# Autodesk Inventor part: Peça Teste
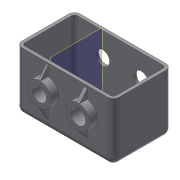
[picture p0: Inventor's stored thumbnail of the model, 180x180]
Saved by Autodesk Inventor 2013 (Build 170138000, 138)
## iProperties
Created: 2013-05
Part Number: Peça Teste
Material: Genérico
Document SubType Name: Modeling
Designer: Draw
Density: 1 g/cm^3
Author: Draw
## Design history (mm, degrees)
sketch "Esboço1"
  geometry: L1 (0, 0)-(500, 0); L2 (500, 0)-(500, 300); L3 (500, 300)-(0, 300); L4 (0, 300)-(0, 0)
  constraints: 8 end point, 2 parallel, 1 horizontal, 1 perpendicular
  dimensions: "d0" = 500 distance of L3.end L2.end; "d1" = 300 distance of L2.end L1.end
extrude "Extrusão1" new body sketch "Esboço1" distance "d2" = 300; taper "d3" = 0 deg
fillet "Arredondamento1" dims "d4" = 30
feature "Casca1" dims "d5" = 15
sketch "Esboço2"
  geometry: L1 (-30, 270)-(-30, 0) reference; C1 r 60.534 at (130, 148.006); C2 r 60.906 at (328.225, 148.006); 1 further point
  constraints: 2 centre point
  dimensions: "d9" = 160 distance from line of L1 C1.centre
extrude "Extrusão2" join sketch "Esboço2" distance "d6" = 40; taper "d7" = 0 deg
node "Plano de trabalho1"
sketch "Esboço3"
  geometry: L1 (-182.528, -70)-(-61.46, -70) reference; L2 (-270, -30)-(0, -30) reference; L3 (-251.657, -30)-(-182.528, -70); L4 (-61.46, -70)-(-8.624, -30); 1 further point
  constraints: 4 end point, 2 point on line
feature "Nervura1" sketch "Esboço3" dims "d10" = 1, "d11" = 10, "d12" = 0, "d13" = 0, "d14" = 1, "d15" = 1
sketch "Esboço4"
  geometry: L1 (-8.199, -110.122)-(8.199, -110.122); L2 (8.199, -110.122)-(8.199, 110.122); L3 (8.199, 110.122)-(-8.199, 110.122); L4 (-8.199, 110.122)-(-8.199, -110.122); L5 (-8.199, -110.122)-(8.199, 110.122); L6 (8.199, -110.122)-(-8.199, 110.122); C1 r 60.906 at (0, 0) reference; 1 further point
  constraints: 12 end point, 2 midpoint, 2 parallel, 1 horizontal, 1 perpendicular
extrude "Extrusão3" join sketch "Esboço4" stored distance "d16" = 58.75; taper "d17" = 0 deg
sketch "Esboço5"
  geometry: L1 (49.77, 0)-(0, 0) reference; L2 (49.77, 0)-(49.77, 40) reference; L3 (0, 0)-(49.77, 40); L4 (-120.703, 40)-(-170.474, 40) reference; L5 (-120.703, 40)-(-120.703, 0) reference; L6 (-170.474, 40)-(-120.703, 40) reference; L7 (-170.474, 0)-(-170.474, 40) reference; L8 (-120.703, 0)-(-170.474, 0) reference; L9 (-170.474, 40)-(-120.703, 0); 1 further point
  constraints: 4 end point
extrude "Extrusão4" cut sketch "Esboço5" stored distance "d18" = 10; taper "d19" = 0 deg
sketch "Esboço6"
  geometry: L1 (336.424, 208.357)-(320.027, 208.357) reference; L2 (320.027, 87.654)-(336.424, 87.654) reference; C1 r 35.894 at (130, 148.006); C2 r 39.42 at (328.225, 148.006); A1 r 60.534 centre (130, 148.006) between (135, 87.679) and (135, 208.333) reference; A2 r 60.906 centre (328.225, 148.006) between (320.027, 208.357) and (320.027, 87.654) reference; A3 r 60.906 centre (328.225, 148.006) between (336.424, 87.654) and (336.424, 208.357) reference; 1 further point
  constraints: 2 centre point, 2 coincident
extrude "Extrusão5" cut sketch "Esboço6" stored distance "d20" = 10; taper "d21" = 0 deg
node "Sólido1"
node "Contorno projetado1"
node "Contorno projetado2"
